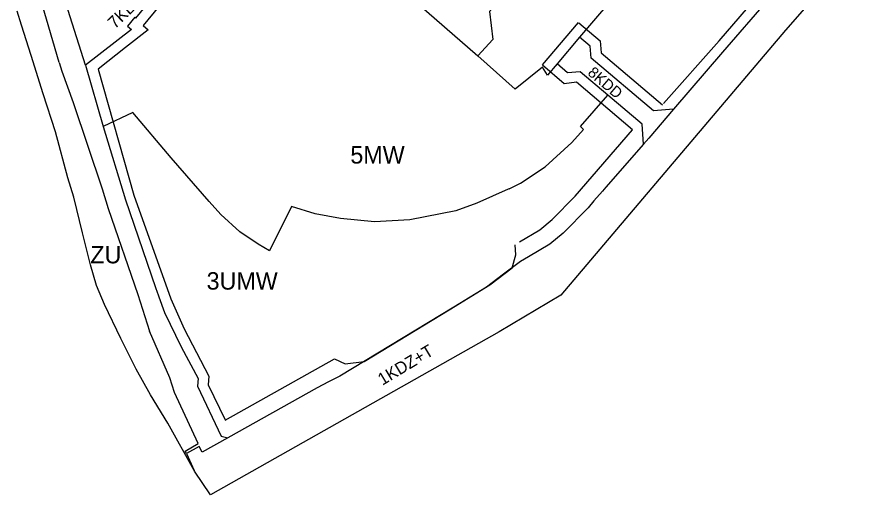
# Model space of a CAD drawing. Extents: x 7426210 to 7427579, y 5548413 to 5549685.
# Drawn here: x 7426628.2 to 7427118.1, y 5548413.3 to 5548687.4 of the extents above; entities that cross this region are included whole.
import ezdxf

# ---------------------------------------------------------------- set-up
doc = ezdxf.new("R2010")
doc.units = 0
for name, color, linetype in [('linie_rozgraniczajace', 7, 'Continuous'), ('linie_zabudowy_nieprzekraczalne', 7, 'Continuous'), ('linie_zabudowy_obowiazujace', 7, 'Continuous'), ('oznaczenia_przeznaczen', 7, 'Continuous')]:
    doc.layers.add(name, color=color, linetype=linetype)

msp = doc.modelspace()

# ---------------------------------------------------------------- linework, layer by layer
at = {"layer": 'linie_rozgraniczajace'}
for p, q in [((7426652.39, 5548661.45), (7426628.81, 5548742.31)), ((7426630.8, 5548682.71), (7426628.23, 5548690.91)), ((7426636.24, 5548665.47), (7426630.8, 5548682.71)), ((7426957.41, 5548670.75), (7426951.39, 5548675.84)), ((7426957.98, 5548663.89), (7426957.41, 5548670.75)), ((7426643.22, 5548643.43), (7426636.24, 5548665.47)), ((7426993.73, 5548633.63), (7426957.98, 5548663.89)), ((7426667.6, 5548659.8), (7426677.75, 5548624.69)), ((7426944.49, 5548655.48), (7426938.43, 5548660.61)), ((7426951.73, 5548656.08), (7426944.49, 5548655.48)), ((7426650.32, 5548621.6), (7426643.22, 5548643.43)), ((7426694.65, 5548632.62), (7426677.75, 5548624.69)), ((7426716.8, 5548606.76), (7426694.65, 5548632.62)), ((7427005.36, 5548634.62), (7426993.73, 5548633.63)), ((7426657.35, 5548595.22), (7426650.32, 5548621.6)), ((7426677.75, 5548624.69), (7426690.52, 5548582.68)), ((7426988.1, 5548614.62), (7426987.21, 5548626.05)), ((7426738.52, 5548581.58), (7426716.8, 5548606.76)), ((7426660.75, 5548584.03), (7426657.35, 5548595.22)), ((7426665.9, 5548563.68), (7426660.75, 5548584.03)), ((7426690.52, 5548582.68), (7426707.82, 5548532.28)), ((7426745.22, 5548574.2), (7426738.52, 5548581.58)), ((7426756.21, 5548564.28), (7426745.22, 5548574.2)), ((7426670.35, 5548545.37), (7426665.9, 5548563.68)), ((7426766.74, 5548557.07), (7426756.21, 5548564.28)), ((7426773.19, 5548553.25), (7426766.74, 5548557.07)), ((7426673.9, 5548533.5), (7426670.35, 5548545.37)), ((7426678.44, 5548522.54), (7426673.9, 5548533.5)), ((7426707.82, 5548532.28), (7426708.72, 5548529.65)), ((7426708.72, 5548529.65), (7426709.22, 5548528.15)), ((7426709.22, 5548528.15), (7426709.63, 5548527.02)), ((7426709.63, 5548527.02), (7426712.93, 5548517.87)), ((7426687.85, 5548503.08), (7426678.44, 5548522.54)), ((7426712.93, 5548517.87), (7426722.43, 5548498.26)), ((7426696.65, 5548485.51), (7426687.85, 5548503.08)), ((7426722.43, 5548498.26), (7426732.3, 5548480.17)), ((7426704.97, 5548470.79), (7426696.65, 5548485.51)), ((7426732.3, 5548480.17), (7426731.92, 5548475.7)), ((7426731.92, 5548475.7), (7426745.55, 5548447.03)), ((7426714.91, 5548454.5), (7426704.97, 5548470.79)), ((7426745.55, 5548447.03), (7426749.29, 5548446.05)), ((7426739.32, 5548413.29), (7426730.2, 5548426.97))]:
    msp.add_line(p, q, dxfattribs=at)
for points in [[(7427125.5, 5548914.1), (7427133.33, 5548907.25), (7427142.99, 5548898.8), (7427149.56, 5548893.06), (7427151.81, 5548891.16), (7427162.67, 5548882), (7427179.08, 5548867.84), (7427181.01, 5548852.4), (7427178.29, 5548845.49), (7427170.15, 5548833.9), (7427170.28, 5548833.79), (7427170.23, 5548833.74), (7427164.3, 5548826.85), (7427163.75, 5548827.34), (7427162.99, 5548826.5), (7427157.96, 5548819.2), (7427151.08, 5548803.16), (7427112.12, 5548758.07), (7427033.49, 5548667.27), (7427005.36, 5548634.62), (7426991.04, 5548617.99)], [(7427214.1, 5548847.4), (7427175.3, 5548800.83), (7427120.9, 5548738.6), (7427069.59, 5548679.9)], [(7426918.65, 5548765.3), (7426926.31, 5548766.21), (7426939.27, 5548735.51), (7426899.66, 5548690.67), (7426901.57, 5548674.58), (7426892.99, 5548665.11)], [(7426841.31, 5548750.46), (7426843.94, 5548750.31), (7426844.06, 5548748.51), (7426853.17, 5548722.04), (7426839.96, 5548711.56), (7426892.99, 5548665.11), (7426914.38, 5548645.99)], [(7426667.6, 5548659.8), (7426658.78, 5548687.58), (7426649.57, 5548716.59), (7426640.13, 5548746.31)], [(7426696.44, 5548686.9), (7426724.16, 5548720.58), (7426738.22, 5548735.84), (7426746.17, 5548740.88), (7426754.76, 5548744.7), (7426763.06, 5548747.64)], [(7427000.95, 5548740.85), (7427003.3, 5548736.82), (7426951.39, 5548675.84), (7426938.43, 5548660.61), (7426932.94, 5548654.17), (7426930.13, 5548658.69), (7426914.38, 5548645.99)], [(7426696.44, 5548686.9), (7426695.97, 5548687.3), (7426691.69, 5548682.24), (7426694.01, 5548680.29), (7426694.05, 5548680.26), (7426667.6, 5548659.8)], [(7427069.59, 5548679.9), (7426940.58, 5548527.83), (7426905.22, 5548506.79), (7426739.32, 5548413.29)], [(7426652.39, 5548661.45), (7426654.01, 5548656.49), (7426660.51, 5548638.35), (7426677.16, 5548588.99), (7426680.55, 5548577.57), (7426697.57, 5548528.36), (7426704.25, 5548507.16)], [(7426987.21, 5548626.05), (7426967.65, 5548642.6), (7426951.73, 5548656.08)], [(7426910.83, 5548588.94), (7426917.42, 5548592.17), (7426931.55, 5548601.43), (7426946.81, 5548615.47), (7426953.69, 5548622.85), (7426951.84, 5548624.58), (7426967.65, 5548642.6)], [(7426991.04, 5548617.99), (7426988.1, 5548614.62), (7426966.47, 5548589.82), (7426964.46, 5548587.53), (7426959.61, 5548581.94), (7426956.26, 5548577.98), (7426941.99, 5548563.46)], [(7426910.83, 5548588.94), (7426910.42, 5548588.69), (7426892.38, 5548580.66), (7426880.23, 5548576.34), (7426853.84, 5548571.02), (7426833.53, 5548569.95), (7426813.98, 5548571.82), (7426799.42, 5548574.55), (7426785.93, 5548578.71), (7426773.19, 5548553.25)], [(7426941.99, 5548563.46), (7426934.24, 5548557.18), (7426922, 5548549.95), (7426917.46, 5548547.26), (7426907.66, 5548539.85), (7426897.84, 5548532.42), (7426879.21, 5548520.97), (7426813.69, 5548481.5), (7426807.11, 5548478.11), (7426800.52, 5548474.72), (7426749.29, 5548446.05), (7426734.65, 5548437.85), (7426732.8, 5548441.16), (7426725.52, 5548437.02), (7426730.03, 5548427.27)], [(7426725.52, 5548437.02), (7426724.83, 5548438.39), (7426732.32, 5548442.87), (7426718.67, 5548472.02), (7426715.93, 5548480.46), (7426704.25, 5548507.16)], [(7426730.2, 5548426.97), (7426730.03, 5548427.27), (7426714.91, 5548454.5)]]:
    msp.add_lwpolyline(points, dxfattribs=at)
at = {"layer": 'linie_zabudowy_nieprzekraczalne'}
msp.add_line((7426930.14, 5548660.02), (7426950.79, 5548684.25), dxfattribs=at)
for points in [[(7426765.07, 5548741.99), (7426756.99, 5548739.12), (7426749.01, 5548735.57), (7426742.1, 5548731.2), (7426728.69, 5548716.63), (7426700.63, 5548682.56)], [(7426700.63, 5548682.56), (7426703.6, 5548680.06), (7426690.48, 5548669.91)], [(7426950.85, 5548684.15), (7426963.18, 5548673.72), (7426963.75, 5548666.87), (7426998.91, 5548637.1)], [(7426690.48, 5548669.91), (7426674.73, 5548657.58), (7426695.26, 5548585.29), (7426716.56, 5548525.86), (7426724.15, 5548508.65), (7426738.43, 5548481.4), (7426737.98, 5548476.42), (7426747.81, 5548456.44)], [(7426949.49, 5548650.12), (7426942.53, 5548649.12), (7426930.13, 5548659.85)], [(7426981.74, 5548622.75), (7426949.49, 5548650.12)], [(7426916.91, 5548558.56), (7426928.52, 5548565.41), (7426935.66, 5548571.25), (7426948.87, 5548584.72), (7426981.74, 5548622.75)], [(7426747.86, 5548456.12), (7426810.54, 5548491.43), (7426816.79, 5548488.56), (7426827.6, 5548489.74), (7426876.43, 5548519.48), (7426899.85, 5548533.74), (7426912.56, 5548543.55), (7426914.69, 5548550.99), (7426914.27, 5548556.73)]]:
    msp.add_lwpolyline(points, dxfattribs=at)
at = {"layer": 'linie_zabudowy_obowiazujace'}
msp.add_lwpolyline([(7426999.5, 5548637.91), (7427031.6, 5548673.89), (7427108.64, 5548763.35), (7427150.54, 5548811.58)], dxfattribs=at)

# ---------------------------------------------------------------- texts
at = {"layer": 'oznaczenia_przeznaczen'}
for s, height, rotation, p in [('7KDD', 7, 43.9038, (7426684.42, 5548680.36)), ('8KDD', 6.3, 319.4638, (7426955.54, 5548654.74)), ('1KDZ+T', 7, 31.0089, (7426838.09, 5548475.88))]:
    msp.add_text(s, height=height, rotation=rotation, dxfattribs=at).set_placement(p)
for s, p in [('5MW', (7426819.68, 5548603.39)), ('ZU', (7426670.31, 5548546.14)), ('3UMW', (7426737.11, 5548531.08))]:
    msp.add_text(s, height=10, dxfattribs=at).set_placement(p)

doc.saveas('drawing.dxf')
